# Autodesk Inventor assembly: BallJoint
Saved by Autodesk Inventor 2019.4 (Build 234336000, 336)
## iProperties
Created: 2020-02
Part Number: BallJoint
Document SubType Name: Assembly
Designer: Administrator
Title: BallJoint v14
Author: Administrator
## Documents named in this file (3)
- c:\worker\convert-fusion-r01\tmp\job-1\5\output\files\e4333473-a38b-4431-9958-ad24a2f67704\BallJoint v14_1.iam
- c:\worker\convert-fusion-r01\tmp\job-1\5\output\files\e4333473-a38b-4431-9958-ad24a2f67704\Component1_1.ipt
- c:\worker\convert-fusion-r01\tmp\job-1\5\output\files\e4333473-a38b-4431-9958-ad24a2f67704\Component2_1.ipt
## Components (2 placed, 2 different names)
1. Component1:1
2. Component2:1
